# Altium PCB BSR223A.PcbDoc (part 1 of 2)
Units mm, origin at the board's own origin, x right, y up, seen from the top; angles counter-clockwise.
Board outline 76.2 x 76.2 mm, 4 copper layers (Top Layer, GND Layer 1, GND Layer 2, Bottom Layer), stack 1.554 mm thick; 57 components, 15 nets, 85 pads, 327 vias.
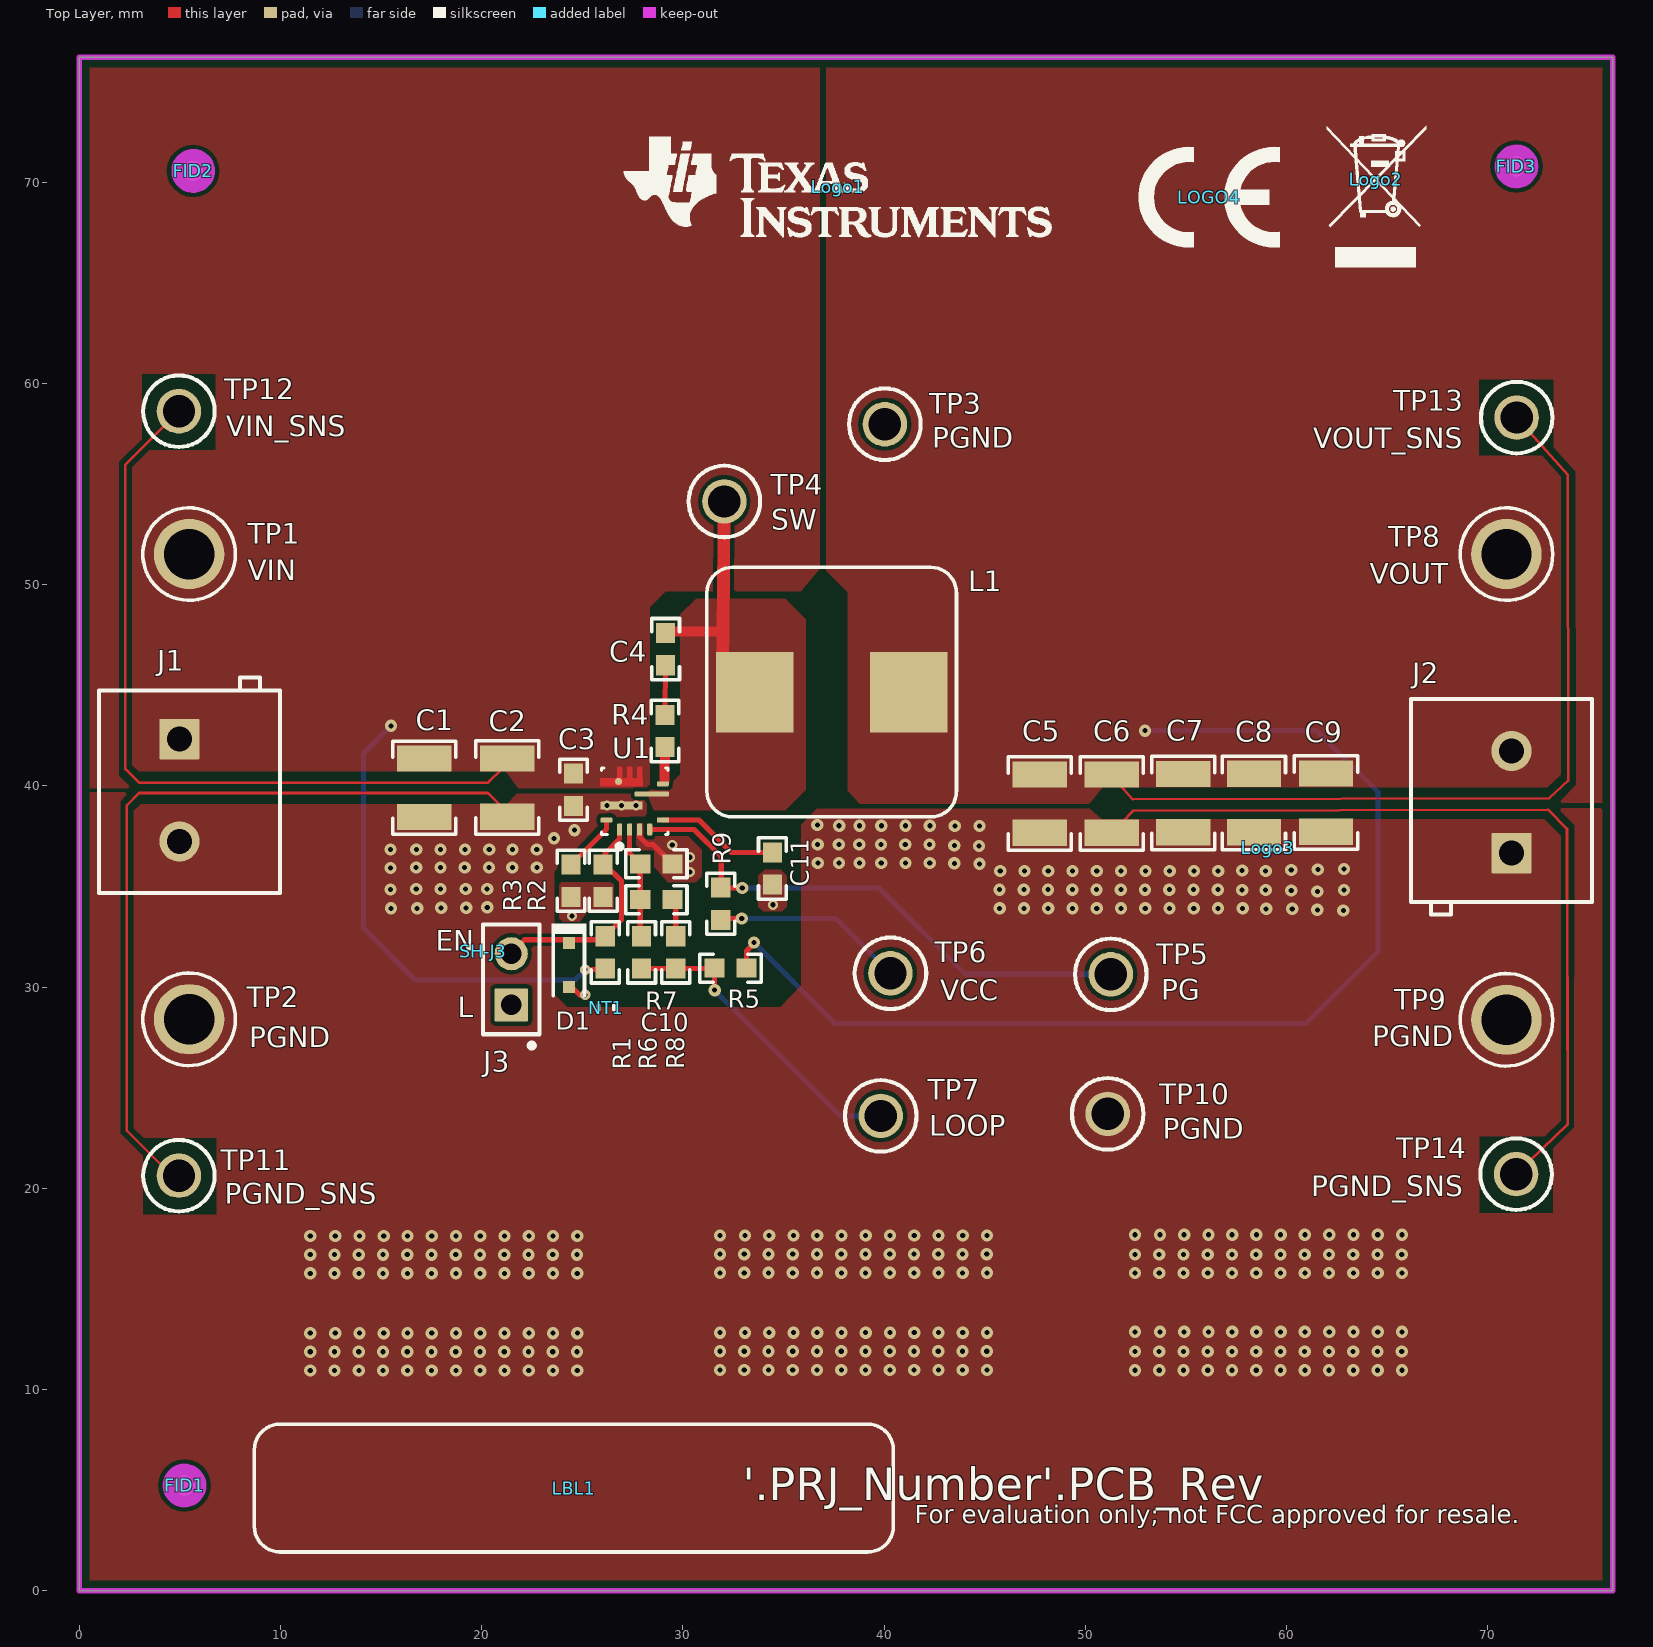
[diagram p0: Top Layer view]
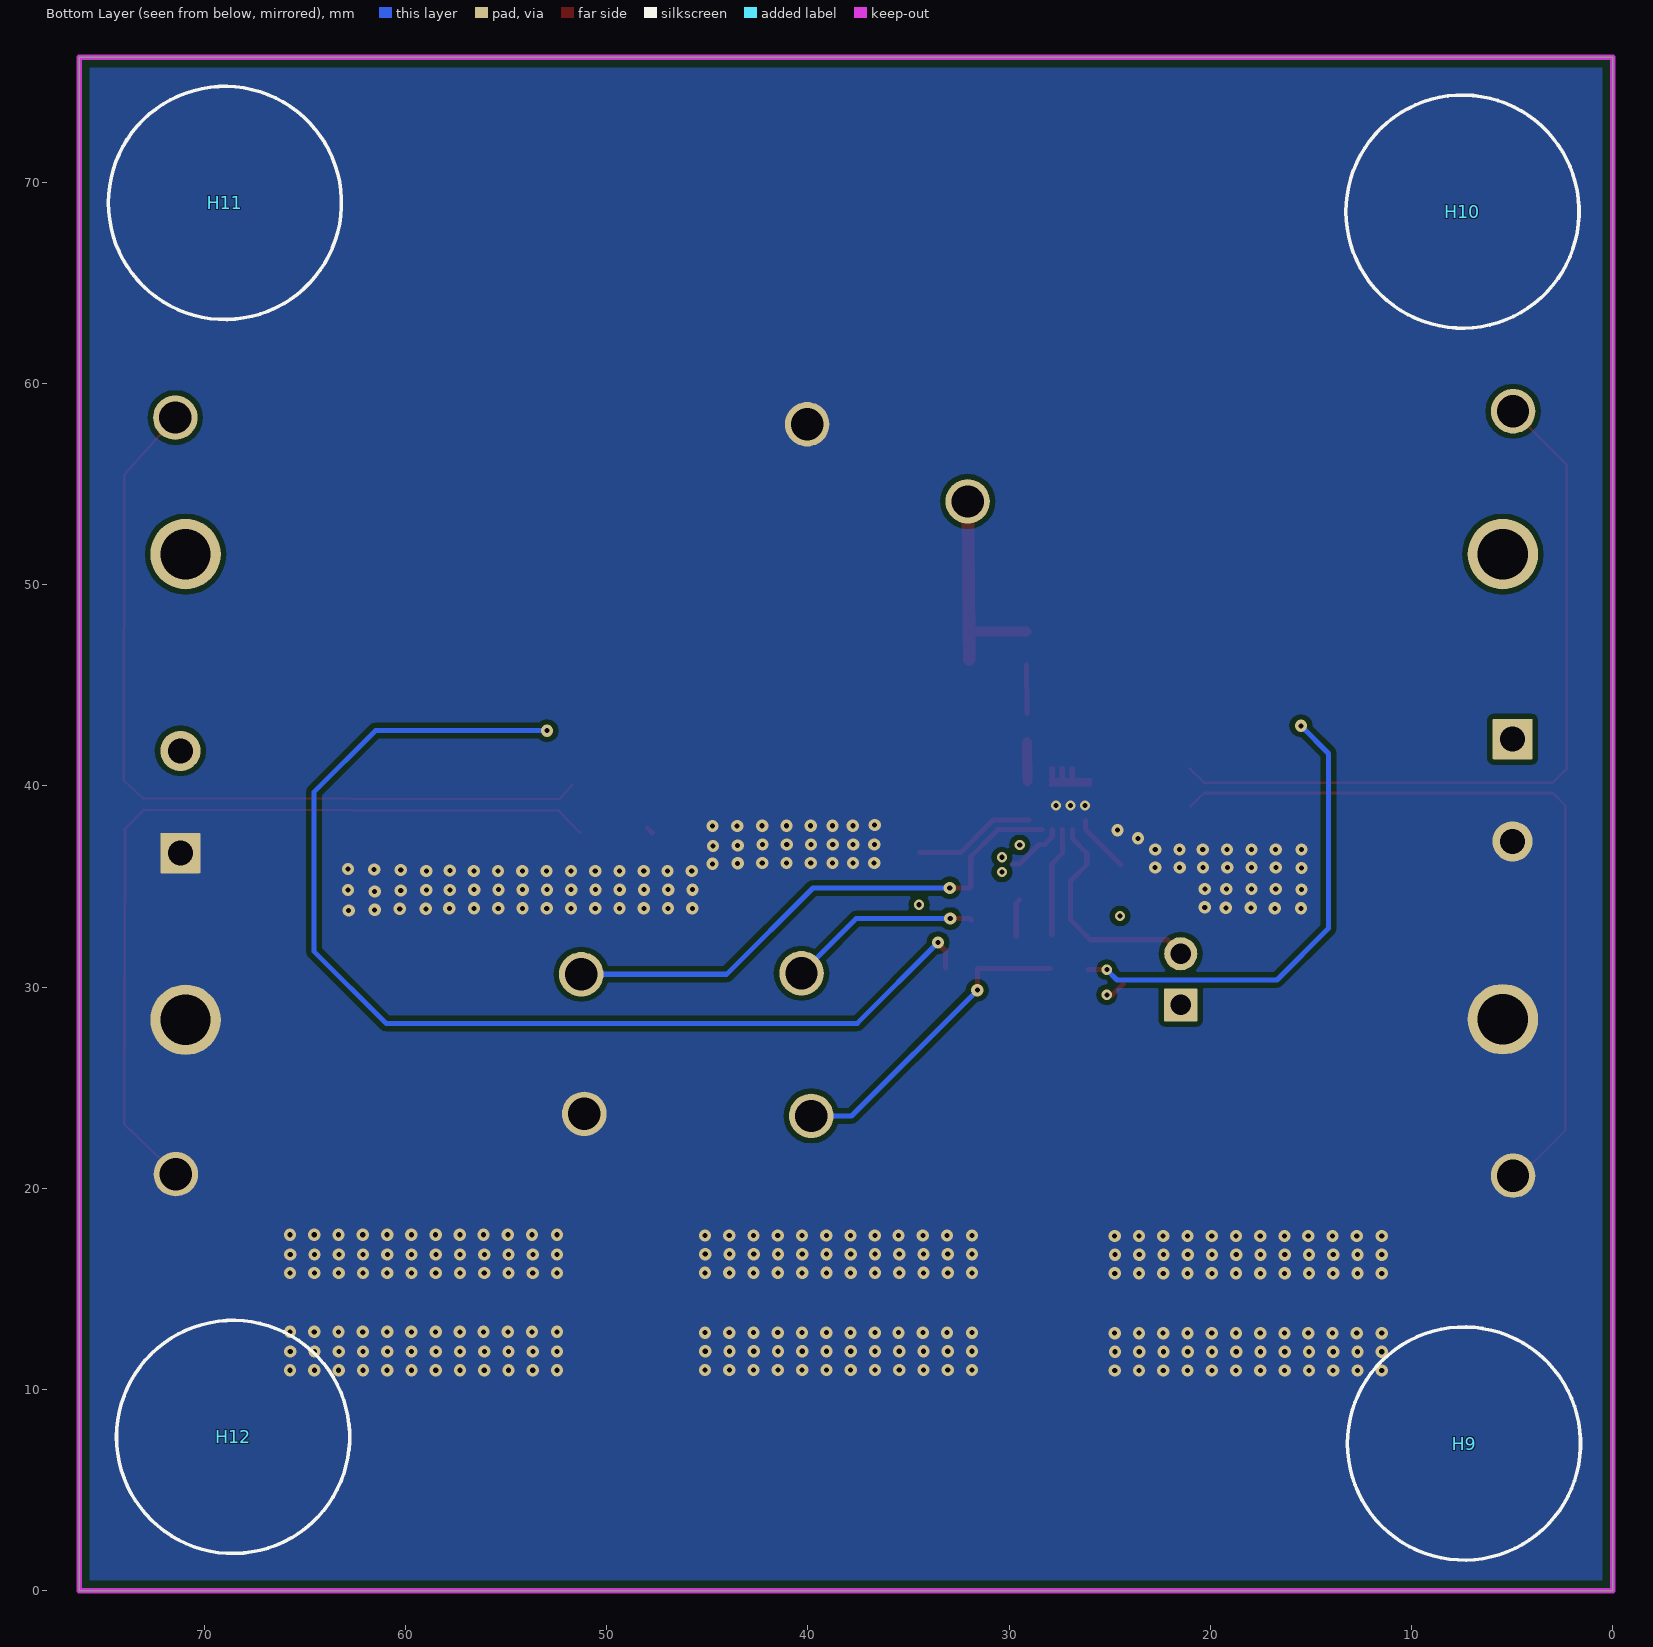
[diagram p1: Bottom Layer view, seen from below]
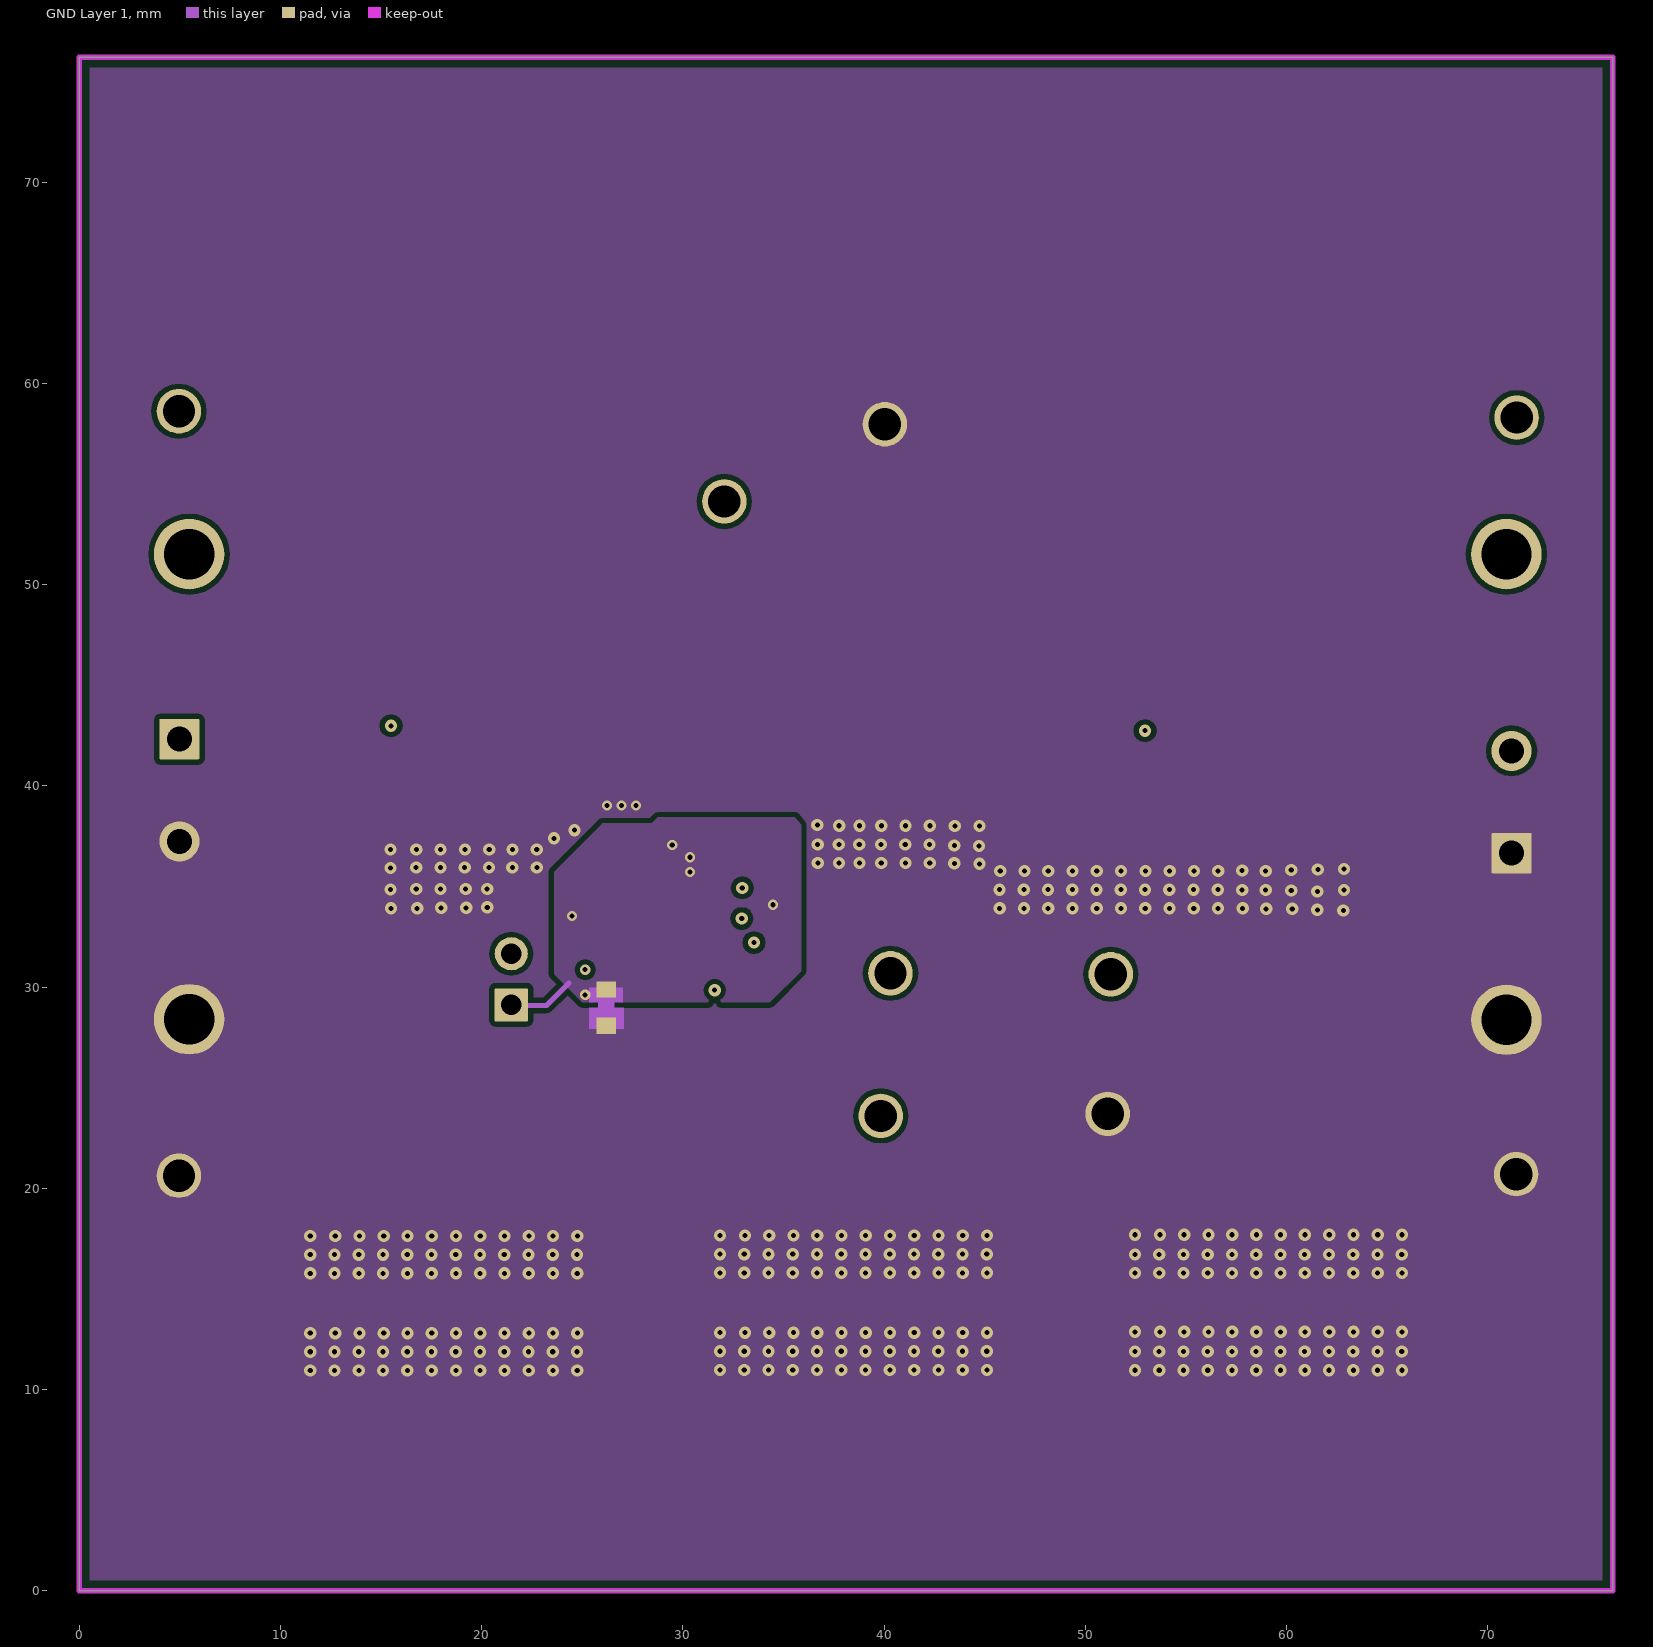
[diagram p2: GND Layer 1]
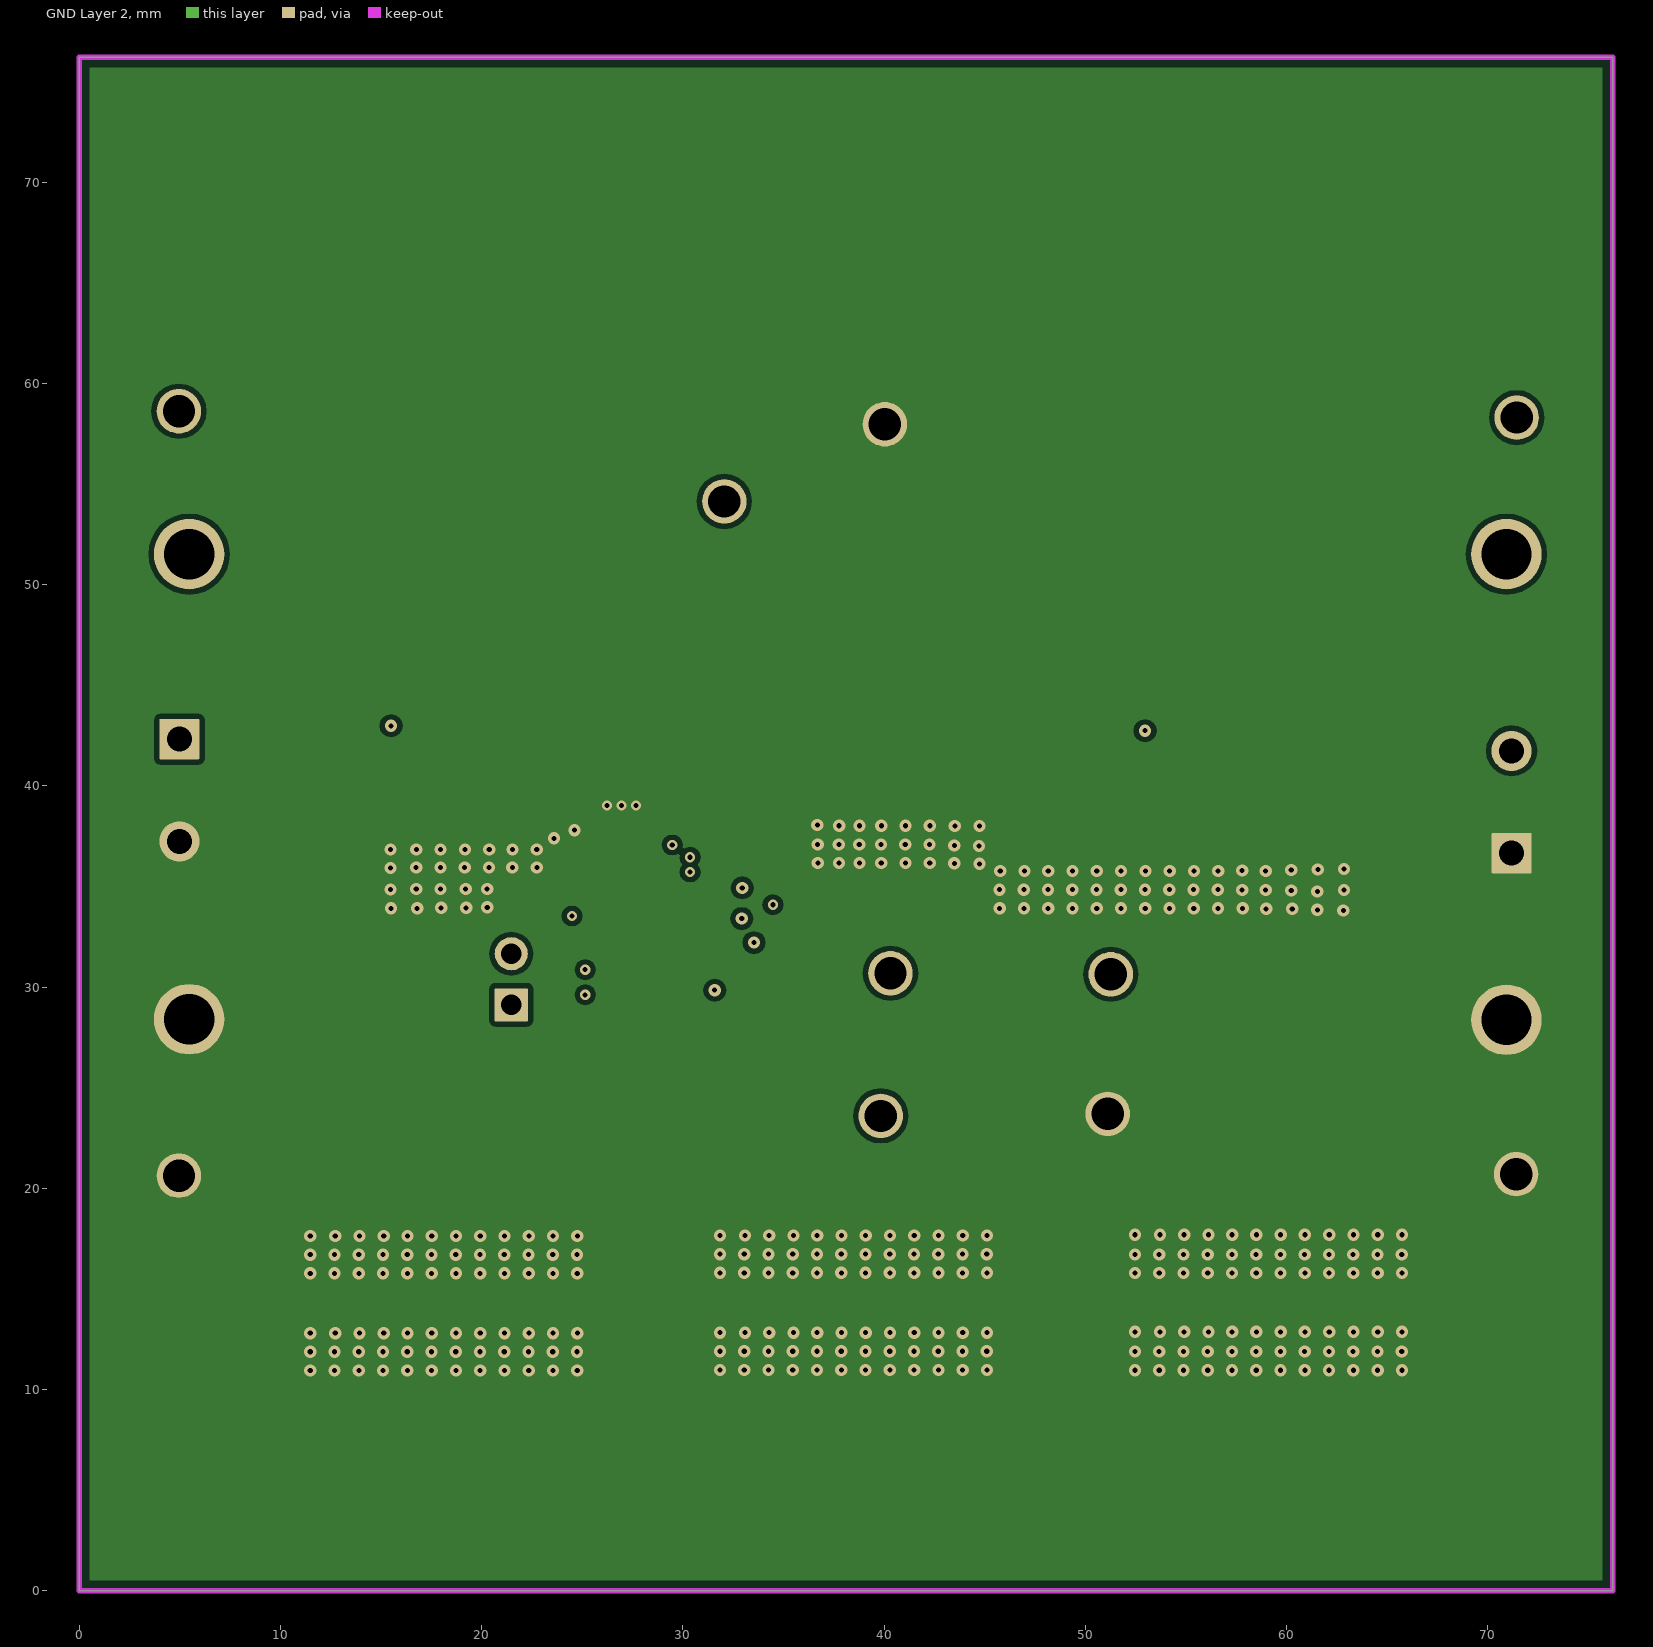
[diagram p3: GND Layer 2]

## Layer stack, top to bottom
Top Solder: solder mask 0.0102, Solder Resist, Dk 3.5
Top Layer: signal copper 0.072
Dielectric1: core 0.1524, FR-4, Dk 4.8
GND Layer 1: signal copper 0.036
Dielectric 3: prepreg 1.0337, Dk 4.8
GND Layer 2: signal copper 0.036
Dielectric 2: core 0.1524, Dk 4.8
Bottom Layer: signal copper 0.072
Bottom Solder: solder mask 0.0102, Solder Resist, Dk 3.5

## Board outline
0,0 76.2,0 76.2,76.2 0,76.2

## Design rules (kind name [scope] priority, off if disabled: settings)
AcuteAngle [All] p1: minimum=4.50000000000000E+0001 checktracksonly=TRUE
AssemblyTestPointUsage [All] p1: valid=2
BoardOutlineClearance BoardOutlineClearance_MountingHoles [OnCopper and InComponentClass('Mounting Holes')] p1: gap=1.016 ignorepadtopadclearanceinfootprint=FALSE
BoardOutlineClearance BoardOutlineClearance_Poly [OnCopper and IsPoly] p2: gap=0.508 ignorepadtopadclearanceinfootprint=FALSE
BoardOutlineClearance [OnCopper and Not InComponentClass('Logo') and not InComponentClass('FiducialMark') and not InRegion(1000,500,4000,800) and not InPoly] p3: gap=0.508 ignorepadtopadclearanceinfootprint=FALSE
Clearance Clearance_1 [All] p1: gap=0.201 ignorepadtopadclearanceinfootprint=FALSE except(0: Arc-SMDPad Arc-Hole Track-Hole SMDPad-Hole THPad-Hole Via-Hole Fill-Hole Poly-Hole Region-Hole Text-Hole; 0.254: Arc-THPad Arc-Via Arc-Text Track-THPad Track-Via Track-Text SMDPad-THPad SMDPad-Text THPad-THPad THPad-Via THPad-Text Via-Via Via-Text Fill-Text Poly-Text Region-Text Text-Text)
Clearance Clearance_Keepouts [((IsTrack Or IsArc) And Not InPoly) And IsFree and IsKeepOut vs ((IsTrack Or IsArc) And Not InPoly) And IsFree and IsKeepOut] p2: gap=0 ignorepadtopadclearanceinfootprint=FALSE
Clearance Clearance_Poly [InPolygon] p3: gap=0.254 ignorepadtopadclearanceinfootprint=FALSE except(0: Arc-Hole Track-Hole SMDPad-Hole THPad-Hole Via-Hole Fill-Hole Poly-Hole Region-Hole Text-Hole)
Clearance Clearance_FiducialMark [IsKeepOut and InComponentClass('FiducialMark') vs IsPad and InComponentClass('FiducialMark')] p4: gap=0 ignorepadtopadclearanceinfootprint=FALSE
Clearance [All] p5: gap=0.2 ignorepadtopadclearanceinfootprint=FALSE except(0: Arc-Hole Track-Hole SMDPad-Hole THPad-Hole Via-Hole Fill-Hole Poly-Hole Region-Hole Text-Hole)
ComponentClearance ComponentClearance_MountingHoles_FiducialMarks [InComponentClass('Mounting Holes') vs InComponentClass('FiducialMark')] p1: gap=0.254 collisioncheckmode=3 verticalgap=0.254 showdistances=FALSE
ComponentClearance ComponentClearance_Shunt [InComponentClass('Header') vs InComponentClass('Shunt')] p2: gap=0 collisioncheckmode=3 verticalgap=0 showdistances=FALSE
ComponentClearance ComponentClearance_Logo [InComponentClass('Logo')] p3: gap=0.254 collisioncheckmode=3 verticalgap=0.254 showdistances=FALSE
ComponentClearance ComponentClearance_ScrewToNut [(HasFootprint('NY PMS 440 0025 PH')) vs (HasFootprint('Keystone_1902C'))] p4: gap=0.127 collisioncheckmode=3 verticalgap=0.254 showdistances=FALSE
ComponentClearance ComponentClearance_MountingHoles [InComponentClass('Mounting Holes')] p5: gap=0.254 collisioncheckmode=3 verticalgap=2540 showdistances=FALSE
ComponentClearance ComponentClearance_SmallPassives [HasFootprint('0201*') or HasFootprint('0402*') or HasFootprint('0508') or HasFootprint('0603*') or HasFootprint('0612') or HasFootprint('0805*') or HasFootprint('0815*') or HasFootprint('0830*') or HasFootprint('1206*') or HasFootprint('1210*') or HasFootprint('1808*') or HasFootprint('1812*') or HasFootprint('1825*') or HasFootprint('2010*') or HasFootprint('2220*') or HasFootprint('2225*') or HasFootprint('2512*') or HasFootprint('2728*') or HasFootprint('3518*') vs HasFootprint('0201*') or HasFootprint('0402*') or HasFootprint('0508') or HasFootprint('0603*') or HasFootprint('0612') or HasFootprint('0805*') or HasFootprint('0815*') or HasFootprint('0830*') or HasFootprint('1206*') or HasFootprint('1210*') or HasFootprint('1808*') or HasFootprint('1812*') or HasFootprint('1825*') or HasFootprint('2010*') or HasFootprint('2220*') or HasFootprint('2225*') or HasFootprint('2512*') or HasFootprint('2728*') or HasFootprint('3518*')] p6: gap=0.254 collisioncheckmode=3 verticalgap=0.254 showdistances=FALSE
ComponentClearance ComponentClearance_THtoSMT [IsThruComponent vs IsSMTComponent] p7: gap=0.254 collisioncheckmode=3 verticalgap=0.762 showdistances=FALSE
ComponentClearance ComponentClearance_THtoTH [IsThruComponent vs IsThruComponent] p8: gap=0.254 collisioncheckmode=3 verticalgap=0.762 showdistances=FALSE
ComponentClearance [All] p9: gap=0.254 collisioncheckmode=3 verticalgap=0.762 showdistances=FALSE
DiffPairsRouting [All] p1: maxlimit=2.54 minlimit=0.254 mostfreqgap=0.254 toplayer_minwidth=0.381 toplayer_maxwidth=0.381 toplayer_prefwidth=0.381 midlayer1_minwidth=0.381 midlayer1_maxwidth=0.381 midlayer1_prefwidth=0.381 midlayer2_minwidth=0.381 midlayer2_maxwidth=0.381 midlayer2_prefwidth=0.381 bottomlayer_minwidth=0.381 bottomlayer_maxwidth=0.381 bottomlayer_prefwidth=0.381 maxuncoupledlength=25.4
FabricationTestPointUsage TestPointUsage [All] p1: valid=2 allowmultiple=FALSE
FabricationTestpoint Testpoint [All] p1: side=3 testpointundercomponent=TRUE minsize=1.016 maxsize=2.54 preferedsize=1.524 minholesize=0 maxholesize=1.016 preferedholesize=0.813 testpointgrid=0.025 allowsidetop=TRUE allowsidebottom=TRUE usegrid=TRUE gridtolerance=0
FanoutControl Fanout_LCC [IsLCC] p1: bgadir=Out bgaviamode=Centered fanoutstyle=Auto fanoutdirection=Alternating viagrid=0.025 // Fanout_LCC (Default Rule)
FanoutControl Fanout_BGA [IsBGA] p2: bgadir=Out bgaviamode=Centered fanoutstyle=Auto fanoutdirection=Alternating viagrid=0.025 // Fanout_BGA (Default Rule)
FanoutControl Fanout_Default [All] p4: bgadir=Out bgaviamode=Centered fanoutstyle=Auto fanoutdirection=Alternating viagrid=0.025 // Fanout_Default (Default Rule)
FanoutControl Fanout_Small [(CompPinCount < 5)] p5: bgadir=Out bgaviamode=Centered fanoutstyle=Auto fanoutdirection=OutThenIn viagrid=0.025 // Fanout_Small (Default Rule)
HoleSize [All] p1: absolutevalues=TRUE maxlimit=6.375 minlimit=0.2 maxpercent=80.000 minpercent=20.000
MinimumAnnularRing MinimumAnnularRing_ThermalPadVias [IsVia and InAnyComponent] p1: minimumring=0.127
MinimumAnnularRing [All] p2: minimumring=0.127
MinimumSolderMaskSliver MinimumSolderMaskSliver_Logo [InComponentClass('Logo') vs InComponentClass('Logo')] p1: minsoldermaskwidth=0.018
MinimumSolderMaskSliver [All] p2: minsoldermaskwidth=0.003
PlaneConnect [All] p1: planeconnectstyle=Relief reliefexpansion=0.254 reliefentries=4 reliefconductorwidth=0.254 reliefairgap=0.254
PolygonConnect [All] p1: connectstyle=Direct reliefconductorwidth=0.254 reliefentries=4 polygonreliefangle="90 Angle" airgapwidth=0.254
RoutingVias ThermalPadVias [IsVia and InAnyComponent] p1: holewidth=0.2 width=0.5 viastyle="Through Hole" minholewidth=0.2 minwidth=0.5 maxholewidth=0.33 maxwidth=0.6
RoutingVias [All] p2: holewidth=0.406 width=0.864 viastyle="Through Hole" minholewidth=0.2 minwidth=0.508 maxholewidth=1.016 maxwidth=1.651
SilkToBoardRegionClearance [Not ((IsComment or IsDesignator) And (Hide <> 'False')) and not InRegion(1000,500,4000,800)] p1:
SilkToSilkClearance SilkToSilkClearance_Pb-FreeLogo [(HasFootprint('Pb-Free_Overlay_Medium') OR HasFootprint('Pb-Free_Overlay_Small')) vs (HasFootprint('Pb-Free_Overlay_Medium') OR HasFootprint('Pb-Free_Overlay_Small'))] p1: silktosilkclearance=0
SilkToSilkClearance [All] p2: silktosilkclearance=0
SilkToSolderMaskClearance SilkToComponentPadClearance [(IsPad or IsFill or IsRegion) and InAnycomponent] p1: minsilkscreentomaskgap=0 clearancetoexposedcopper=TRUE
SilkToSolderMaskClearance "Silk to Solder Mask Opening" [All] p2: minsilkscreentomaskgap=0 clearancetoexposedcopper=FALSE
SolderMaskExpansion [All] p1: expansion=0.05 istentingtop=FALSE
Width [All] p1: maxlimit=2.54 minlimit=0.076 preferedwidth=0.254 midlayer1_minwidth=0.152 midlayer2_minwidth=0.152 bottomlayer_minwidth=0.152 minimp=50.000000 maximp=50.000000 favimp=50.000000 checkconnectedcopper=TRUE
15 further rules are at their usual default settings.

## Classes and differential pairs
component class Shunt: SH-J3
component class Label: LBL1
component class FiducialMark: FID1 FID2 FID3
component class Header: J3
component class AssemblyNote: ZZ2 ZZ3 ZZ4
component class BSR223A_Hardware: FID1 FID2 FID3 H9 H10 H11 H12 LBL1 Logo1 Logo2 Logo3 LOGO4 SH-J3 ZZ2 ZZ3 ZZ4
component class Logo: Logo1
component class BSR223A: C1 C2 C3 C4 C5 C6 C7 C8 C9 C10 C11 D1 J1 J2 J3 L1 NT1 R1 R2 R3 R4 R5 R6 R7 R8 R9 TP1 TP2 TP3 TP4 TP5 TP6 TP7 TP8 TP9 TP10 TP11 TP12 TP13 TP14 U1

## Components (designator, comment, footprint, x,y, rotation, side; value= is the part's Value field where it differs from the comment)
C1 "GRM32ER7YA106KA12L" 1210_270 17.145,39.903 r90 top value=10uF
C2 "GRM32ER7YA106KA12L" 1210_270 21.265,39.911 r90 top value=10uF
C3 "885012206095" 0603 24.562,39.802 r90 top value=0.1uF
C4 "885012206095" 0603 29.134,46.787 r270 top value=0.1uF
C5 "GRM32ER71E226KE15L" 1210_270 47.727,39.116 r270 top value=22uF
C6 "GRM32ER71E226KE15L" 1210_270 51.308,39.116 r270 top value=22uF
C7 "GRM32ER71E226KE15L" 1210_270 54.864,39.141 r270 top value=22uF
C8 "GRM32ER71E226KE15L" 1210_270 58.369,39.144 r270 top value=22uF
C9 "GRM32ER71E226KE15L" 1210_270 61.951,39.167 r270 top value=22uF
C10 "GRM1885C1H151JA01D" 0603 28.677,34.341 r180 top value=150pF
C11 "C1608X7R1H473K080AA" 0603 34.442,35.89 r270 top value=0.047uF
D1 "MMSZ5231BS-7-F" SOD-323 24.331,31.097 r270 top value=5.1V
FID1 "Fiducial" Fiducial10-20 5.232,5.232 r0 top
FID2 "Fiducial" Fiducial10-20 5.662,70.551 r0 top
FID3 "Fiducial" Fiducial10-20 71.412,70.777 r0 top
H9 "SJ-5303 (CLEAR)" Bumpon_SJ5003Transparent 7.391,7.315 r180 bottom
H10 "SJ-5303 (CLEAR)" Bumpon_SJ5003Transparent 7.468,68.529 r180 bottom
H11 "SJ-5303 (CLEAR)" Bumpon_SJ5003Transparent 68.961,68.961 r180 bottom
H12 "SJ-5303 (CLEAR)" Bumpon_SJ5003Transparent 68.555,7.645 r180 bottom
J1 "ED120/2DS" On-Shore_ED120_2DS 4.978,39.776 r270 top
J2 "ED120/2DS" On-Shore_ED120_2DS 71.171,39.192 r90 top
J3 "EN" TSW-102-07-X-S 21.468,30.383 r90 top
L1 "744325330" WE-HC6 37.389,44.653 r0 top value=3.3uH
LBL1 "Label" Label_1250x250 24.577,5.103 r180 top
Logo1 "Texas Instruments" TI_Stacked_Overlay_Small 37.686,69.759 r0 top
Logo2 "WEEE logo" WEEE_Minimum 64.414,70.14 r0 top
Logo3 "FCC disclaimer" FCC_disclaimer 59.068,36.921 r0 top
LOGO4 "CE Mark" CE_Mark_5mm 56.142,69.248 r0 top (schematic designator Logo4)
NT1 "Net-Tie" NetTie_0603 26.187,28.976 r270 top net-tie
R1 "RT0603BRD07169KL" 0603 26.137,31.725 r270 top value=169k
R2 "RT0603BRD0736K1L" 0603 26.035,35.281 r90 top value=36.1k
R3 "RT0603DRE0730K1L" 0603 24.435,35.281 r90 top value=30.1k
R4 "CRCW06030000Z0EA" 0603 29.108,42.723 r90 top value=0
R5 "RT0603DRE0749R9L" 0603 32.36,30.937 r0 top value=49.9
R6 "RT0603DRE0773K2L" 0603 27.94,31.725 r270 top value=73.2k
R7 "RT0603DRE0710KL" 0603 28.677,36.119 r0 top value=10.0k
R8 "RC0603JR-070RL" 0603 29.642,31.725 r270 top value=0
R9 "CRCW0603100KFKEA" 0603 31.877,34.138 r270 top value=100k
SH-J3 "SNT-100-BK-G" SNT-100-BK-G 20.066,31.768 r180 top value=1x2
TP1 "VIN" Keystone1502-2 5.461,51.511 r90 top
TP2 "PGND" Keystone1502-2 5.461,28.397 r90 top
TP3 "PGND" Keystone5011 40.03,57.963 r90 top
TP4 "SW" Keystone5013 32.055,54.127 r90 top
TP5 "PG" Keystone5014 51.257,30.632 r90 top
TP6 "VCC" Keystone5014 40.31,30.683 r90 top
TP7 "LOOP" Keystone5014 39.827,23.597 r90 top
TP8 "VOUT" Keystone1502-2 70.917,51.511 r90 top
TP9 "PGND" Keystone1502-2 70.917,28.372 r90 top
TP10 "PGND" Keystone5011 51.105,23.698 r90 top
TP11 "PGND_SNS" Keystone5011 4.952,20.625 r90 top
TP12 "VIN_SNS" Keystone5010 4.952,58.61 r90 top
TP13 "VOUT_SNS" Keystone5010 71.426,58.293 r90 top
TP14 "PGND_SNS" Keystone5011 71.399,20.701 r90 top
U1 "TPS56837RPAR" RPA0010A-MFG 27.598,39.229 r90 top
ZZ2 "These assemblies are ESD sensitive, ESD precautions shall be observed." AssemblyNote 4.699,97.259 r0 top
ZZ3 "These assemblies must be clean and free from flux and all contaminants. Use of no clean flux is not acceptable." AssemblyNote 4.699,95.01 r0 top
ZZ4 "These assemblies must comply with workmanship standards IPC-A-610 Class 2, unless otherwise specified." AssemblyNote 4.699,92.761 r0 top

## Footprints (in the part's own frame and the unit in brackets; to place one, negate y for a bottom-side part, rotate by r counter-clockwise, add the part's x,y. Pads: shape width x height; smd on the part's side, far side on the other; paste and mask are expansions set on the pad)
0603 [mm] "0603 from SM-752 data"
  rect 1x0.95 smd: 1(-0.8,0) 2(0.8,0)
  silkscreen extent -1.52,-0.69 1.52,0.69, body extent -0.87,-0.47 0.87,0.47, height 1
1210_270 [mm] "1210"
  rect 1.3x2.7 smd: 1(-1.45,0) 2(1.45,0)
  silkscreen extent -2.32,-1.57 2.32,1.57, body extent -1.7,-1.35 1.7,1.35, height 2.7
AssemblyNote [mm] "Assembly Note"
Bumpon_SJ5003Transparent [mil] "3M Hemispherical Bumpon transparent"
  round 1 on Mech4: 0(0,0)
  silkscreen extent -228,-228 228,228, body extent -219,-219 219,219, height 197
CE_Mark_5mm [mm] "Minimum text height for CE Mark"
  silkscreen extent -3.5,-2.5 3.5,2.5
FCC_disclaimer [mm]
Fiducial10-20 [mm]
  round 1 smd mask+0.5: 1(0,0)
  Top Layer keep-out circle w1.178: c0,0 r0.5
Keystone1502-2 [mm] "Double Turret"
  round 3.5 hole 2.5: 1(0,0)
  silkscreen extent -2.3,-2.3 2.3,2.3, body extent -1.6,-1.6 1.59,1.6, height 5.62
Keystone5010 [mil] "Keystone Multipurpose loops"
  round 87 hole 63: 1(0,0)
  silkscreen extent -70,-70 70,70, body extent -63,-63 63,62, height 319
Keystone5011 [mil] "Keystone Multipurpose loops"
  round 87 hole 63: 1(0,0)
  silkscreen extent -70,-70 70,70, body extent -63,-63 63,62, height 319
Keystone5013 [mil] "Keystone Multipurpose loops"
  round 87 hole 63: 1(0,0)
  silkscreen extent -70,-70 70,70, body extent -63,-63 63,62, height 319
Keystone5014 [mil] "Keystone Multipurpose loops"
  round 87 hole 63: 1(0,0)
  silkscreen extent -70,-70 70,70, body extent -63,-63 63,62, height 319
Label_1250x250 [mil] "Thermal Transfer Labels"
  round 1 on Mech13: 0(0,0)
  silkscreen extent -625,-125 625,125, body extent -625,-125 625,125, height 1
NetTie_0603 [mm] "Net Tie 0603 size"
  rect 0.8x0.95 on Mid1 paste-1: 1(-0.9,0) 2(0.9,0)
  GND Layer 1 region: -0.6,0.406 0.6,0.406 0.6,-0.406 -0.6,-0.406
  silkscreen extent -0.1,-0.38 0.1,0.38
On-Shore_ED120_2DS [mm] "ONSHORE"
  rrect5% 2x2 hole 1.25: 1(-2.54,0)
  round 2 hole 1.25: 2(2.54,0)
  silkscreen extent -5.6,-4 5.12,5, body extent -5.78,-4 5.08,5, height 13
RPA0010A-MFG [mm]
  rrect40% 0.6x0.25 smd paste+0 mask+0: 1(-1.4,0.75) 2(-1.4,0.25) 3(-1.4,-0.25) 4(-1.4,-0.75)
  rrect40% 0.25x0.6 smd paste+0 mask+0: 5(-0.93,-1.4) 7(0.87,-1.4) 10(-0.93,1.4)
  rrect40% 0.25x1.7 smd paste-1000 mask+0: 6(0.37,-0.85)
  round 0.35 smd paste+0 mask+0: 8(0.99,0.8)
  rrect25% 0.4x2.1 smd paste-1000 mask+0: 9(-0.21,0.65)
  Top Layer region: 0.8,1.7 0.781,1.696 0.765,1.685 0.754,1.669 0.75,1.65 0.75,1.65 0.75,-0.35 0.754,-0.369 0.765,-0.385 0.781,-0.396 0.8,-0.4 0.8,-0.4 1.15,-0.4 1.15,-0.375 1.66,-0.375 1.685,-0.368 1.703,-0.35 1.71,-0.325 1.71,-0.325 1.71,-0.175 1.706,-0.156 1.695,-0.14 1.679,-0.129 1.66,-0.125 1.66,-0.125 1.15,-0.125 1.15,0.125 1.66,0.125 1.679,0.129 1.695,0.14 1.706,0.156 1.71,0.175 1.71,0.175 1.71,0.325 1.703,0.35 1.685,0.368 1.66,0.375 1.66,0.375 1.15,0.375 1.15,0.625 1.66,0.625 1.679,0.629 1.695,0.64 1.706,0.656 1.71,0.675 1.71,0.675 1.71,0.825 1.703,0.85 1.685,0.868 1.66,0.875 1.66,0.875 1.2,0.875 1.181,0.879 1.165,0.89 1.154,0.906 1.15,0.925 1.15,0.925 1.15,1.65 1.143,1.675 1.125,1.693 1.1,1.7 1.1,1.7
  silkscreen extent -2.37,-1.66 1.65,1.65, body extent -1.8,-1.8 1.81,1.8, height 0.25
SNT-100-BK-G [mil] "Samtec STEP model"
  round 1 on Mech3: 0(0,0)
  body extent -100,-50 100,50, height 344
SOD-323 [mm] "NXP recommended land pattern"
  rect 0.6x0.6 smd paste-0.05: 1(-1.1,0) 2(1.1,0)
  silkscreen extent -2.06,-0.86 1.53,0.86, body extent -1.3,-0.67 1.3,0.68, height 1.1
TI_Stacked_Overlay_Small [mm]
  silkscreen extent -10.63,-2.49 10.63,2.49
TSW-102-07-X-S [mm] "Samtec 100 mil 1x2 head, 230 mil above insulator"
  rrect6% 1.65x1.65 hole 1.016: 1(-1.27,0)
  round 1.65 hole 1.016: 2(1.27,0)
  silkscreen extent -3.42,-1.4 2.72,1.4, body extent -2.54,-1.27 2.54,1.27, height 8.38
WE-HC6 [mm] "Wurth Electronik recommended land pattern"
  rect 3.85x4 smd: 1(-3.825,0) 2(3.825,0)
  silkscreen extent -6.2,-6.2 6.2,6.2, body extent -5.76,-5.36 5.74,5.34, height 5
WEEE_Minimum [mm] "WEEElie bin"
  silkscreen extent -2.42,-4.38 2.52,2.65

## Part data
C1 C2: library part CMP-0009233-2, "CAP, CERM, 10 uF, 35 V, +/- 10%, X7R, 1210", Cap_Case=1210, Manufacturer=MuRata, Supplier Part Number 1=490-5314-1-ND, TempCo=X7R, Tolerance_%=10%, Value1=Unknown, Value2=35V, ValueDisplayed=10uF
C3 C4: library part CMP-0006837-4, "CAP, CERM, 0.1 uF, 50 V, +/- 10%, X7R, 0603", Cap_Case=0603, Manufacturer="Wurth Elektronik", TempCo=X7R, Tolerance_%=10%, Value1=Unknown, Value2=50V, ValueDisplayed=0.1uF
C5 C6 C7 C8 C9: library part CMP-0009224-2, "CAP, CERM, 22 uF, 25 V, +/- 10%, X7R, 1210", Cap_Case=1210, Manufacturer=MuRata, Supplier Part Number 1=490-5313-1-ND, TempCo=X7R, Tolerance_%=10%, Value1=Unknown, Value2=25V, ValueDisplayed=22uF
C10: library part CMP-0007185-2, "CAP, CERM, 150 pF, 50 V, +/- 5%, C0G/NP0, 0603", Cap_Case=0603, Manufacturer=MuRata, Supplier Part Number 1=490-1431-1-ND, TempCo=C0G/NP0, Tolerance_%=5%, Value1=Unknown, Value2=50V, ValueDisplayed=150pF
C11: library part CMP-0007049-4, "CAP, CERM, 0.047 uF, 50 V, +/- 10%, X7R, 0603", Cap_Case=0603, Manufacturer=TDK, Supplier Part Number 1=445-1313-1-ND, TempCo=X7R, Tolerance_%=10%, Value1="0.049007 ohm", Value2=50V, ValueDisplayed=0.047uF
D1: library part CMP-0005854-3, "Diode, Zener, 5.1 V, 200 mW, SOD-323", Manufacturer="Diodes Inc.", Power_W=200mW, Value1=0.2W
FID1 FID2 FID3: library part CMP-0077181-1, "Fiducial mark.  There is nothing to buy or mount.", Manufacturer=N/A
H9 H10 H11 H12: "Bumpon, Hemisphere, 0.44 X 0.20, Clear", Manufacturer=3M, Supplier Part Number 1=SJ5303-7-ND
J1 J2: library part CMP-0074910-1, "Terminal Block, 5.08 mm, 2x1, Brass, TH", Color=Blue, Current_A=15A, Manufacturer="On-Shore Technology", Supplier Part Number 1=ED1609-ND, Voltage_V=300V
J3: library part CMP-0075405-1, "Header, 100mil, 2x1, Gold, TH", Color=Black, Current_A=6.3A, Manufacturer=Samtec, PartNumber=TSW-102-07-G-S, Supplier Part Number 1=SAM1029-02-ND, Voltage_V=550V
L1: library part CMP-0063965-1, "Inductor, Shielded Drum Core, Superflux, 3.3 uH, 12 A, 0.0059 ohm, SMD", Manufacturer="Wurth Elektronik", Supplier Part Number 1=732-1169-1-ND, Value1="0.0059 ohm", Value2=12A, ValueDisplayed=3.3uH
LBL1: library part CMP-0003624-1, "Thermal Transfer Printable Labels, 1.250\" W x 0.250\" H - 10,000 per roll", Manufacturer=Brady, PartNumber=THT-13-457-10, Supplier Part Number 1=04H3909
Logo1: library part CMP-0074838-1, "Texas Instrument Corporate Signature"
Logo2: library part CMP-0074769-1
Logo3: library part CMP-0074847-1, "FCC_disclaimer"
LOGO4: library part CMP-0074844-1
NT1: library part CMP-0078142-1, "Single point connection between nets.", Manufacturer=N/A
R1: library part CMP-0023796-3, "RES, 169 k, 0.1%, 0.1 W, 0603", Manufacturer="Yageo America", Power_W=100mW, TempCo="25 ppm/C", Tolerance_%=0.1%, Value2=0.1W, Value_Code=169k
R2: library part CMP-0024154-3, "RES, 36.1 k, 0.1%, 0.1 W, 0603", Manufacturer="Yageo America", Power_W=100mW, TempCo="25 ppm/C", Tolerance_%=0.1%, Value2=0.1W, Value_Code=36k1, ValueDisplayed=36.1k
R3: library part CMP-0025121-3, "RES, 30.1 k, 0.5%, 0.1 W, 0603", Manufacturer="Yageo America", Power_W=100mW, TempCo="50 ppm/C", Tolerance_%=0.5%, Value2=0.1W, Value_Code=30k1, ValueDisplayed=30.1k
R4: "RES, 0, 5%, 0.1 W, 0603", Manufacturer=Vishay-Dale, Power_W=0.1, Supplier Part Number 1=541-0.0GCT-ND, TempCo="200 ppm/C", Tolerance_%=5, Value1=5%, Value2=0.1W, Value_Code=0000, ValueDisplayed=0
R5: library part CMP-0025334-3, "RES, 49.9, 0.5%, 0.1 W, 0603", Manufacturer="Yageo America", Power_W=100mW, TempCo="50 ppm/C", Tolerance_%=0.5%, Value2=0.1W, Value_Code=49R9, ValueDisplayed=49.9
R6: library part CMP-0025549-3, "RES, 73.2 k, 0.5%, 0.1 W, 0603", Manufacturer="Yageo America", Power_W=100mW, TempCo="50 ppm/C", Tolerance_%=0.5%, Value2=0.1W, Value_Code=73k2, ValueDisplayed=73.2k
R7: library part CMP-0024586-3, "RES, 10.0 k, 0.5%, 0.1 W, 0603", Manufacturer="Yageo America", Power_W=100mW, Supplier Part Number 1=603-RT0603DRE0710KL, TempCo="50 ppm/C", Tolerance_%=0.5%, Value2=0.1W, Value_Code=10k0, ValueDisplayed=10.0k
R8: library part CMP-0025885-5, "RES, 0, 5%, 0.1 W, 0603", Manufacturer=Yageo, Power_W=100mW, Supplier Part Number 1=311-0.0GRCT-ND, TempCo="200 ppm/C", Tolerance_%=5%, Value2=0.1W, Value_Code=0000, ValueDisplayed=0
R9: library part CMP-0021990-3, "RES, 100 k, 1%, 0.1 W, 0603", Manufacturer=Vishay-Dale, Power_W=100mW, Supplier Part Number 1=541-100KHCT-ND, TempCo="100 ppm/C", Tolerance_%=1%, Value2=0.1W, Value_Code=100k
SH-J3: library part CMP-0003623-3, "Shunt, 100mil, Gold plated, Black", Alternate Manufacturer=3M, Alternate PartNumber=969102-0000-DA, Manufacturer=Samtec, Supplier Part Number 1=SAM8858-ND
TP1 TP2 TP8 TP9: library part CMP-0055113-1, "Terminal, Turret, TH, Double", Manufacturer=Keystone, PartNumber=1502-2, Supplier Part Number 1=36-1502-2-ND
TP3 TP10 TP11 TP14: library part CMP-0055148-1, "Test Point, Multipurpose, Black, TH", Color=Black, Manufacturer=Keystone, PartNumber=5011, Supplier Part Number 1=36-5011-ND
TP4: library part CMP-0055150-1, "Test Point, Multipurpose, Orange, TH", Color=Orange, Manufacturer=Keystone, PartNumber=5013, Supplier Part Number 1=36-5013-ND
TP5 TP6 TP7: library part CMP-0055151-1, "Test Point, Multipurpose, Yellow, TH", Color=Yellow, Manufacturer=Keystone, PartNumber=5014, Supplier Part Number 1=36-5014-ND
TP12 TP13: library part CMP-0055147-1, "Test Point, Multipurpose, Red, TH", Color=Red, Manufacturer=Keystone, PartNumber=5010, Supplier Part Number 1=36-5010-ND
U1: library part CMP-0094944-3, "4.5-V to 28-V Input, 8-A Synchronous Buck Converter", Manufacturer="Texas Instruments", Max Supply Voltage=28V, Min Supply Voltage=4.5V, Nominal Supply Current=70uA, Operating Temperature Range="-40°C to +150°C", Output Voltage=0.6-13V, Switching Frequency=500/800/1200kHz
ZZ2: library part CMP-0077236-1
ZZ3: library part CMP-0077237-1
ZZ4: library part CMP-0077238-1

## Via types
v1: diameter 0.61, hole 0.254, Top Layer to Bottom Layer, 317 vias
v2: diameter 0.508, hole 0.254, Top Layer to Bottom Layer, 10 vias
